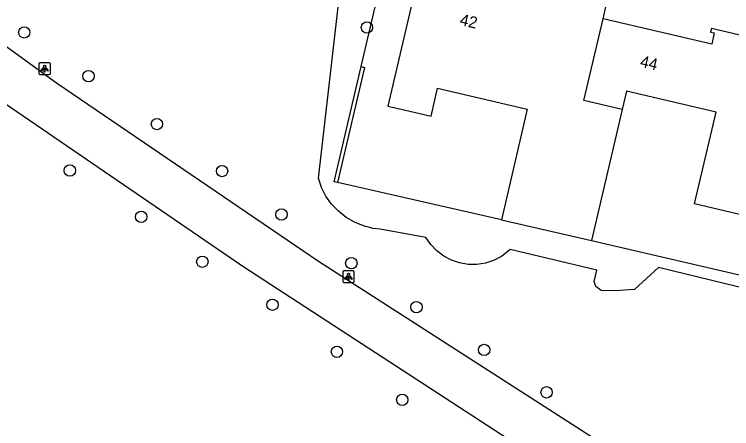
# Model space of a CAD drawing. Extents: x 162186 to 163152, y 385513 to 386513.
# Drawn here: x 162525.5 to 162587.2, y 385631 to 385666.6 of the extents above; entities that cross this region are included whole.
import ezdxf

# ---------------------------------------------------------------- set-up
doc = ezdxf.new("R2010")
doc.units = 0
for name, color, linetype in [('IMGEO_Boom', 7, 'Continuous'), ('IMGEO_Groenvoorziening', 7, 'Continuous'), ('IMGEO_Lichtpunt', 7, 'Continuous'), ('IMGEO_Muur', 7, 'Continuous'), ('IMGEO_Pand', 7, 'Continuous'), ('IMGEO_Pand_nummerreeks', 7, 'Continuous'), ('IMGEO_Voetpad_open', 7, 'Continuous')]:
    doc.layers.add(name, color=color, linetype=linetype)

msp = doc.modelspace()

# ---------------------------------------------------------------- linework, layer by layer
at = {"layer": 'IMGEO_Boom'}
for centre in [(162555.837, 385665.43), (162526.381, 385665.007), (162531.9, 385661.249), (162537.788, 385657.136), (162530.293, 385653.142), (162543.384, 385653.098), (162536.434, 385649.169), (162548.496, 385649.364), (162541.687, 385645.309), (162554.499, 385645.188), (162547.714, 385641.615), (162560.094, 385641.404), (162553.259, 385637.577), (162565.917, 385637.735), (162571.284, 385634.091), (162558.88, 385633.451)]:
    msp.add_circle(centre, 0.489, dxfattribs=at)
at = {"layer": 'IMGEO_Groenvoorziening'}
for points in [[(162591.033, 385642.365), (162580.904, 385644.813), (162578.838, 385642.928), (162577.137, 385642.809), (162575.982, 385642.845), (162575.524, 385643.186), (162575.383, 385643.605), (162575.605, 385644.575), (162568.163, 385646.362), (162567.994, 385646.207), (162567.394, 385645.764), (162566.732, 385645.422), (162566.023, 385645.191), (162565.286, 385645.076), (162564.54, 385645.081), (162563.805, 385645.206), (162563.099, 385645.446), (162562.441, 385645.796), (162561.847, 385646.248), (162561.333, 385646.788), (162560.913, 385647.404), (162556.969, 385648.1), (162556.363, 385648.174), (162555.546, 385648.378), (162554.766, 385648.696), (162554.04, 385649.121), (162553.381, 385649.645), (162552.803, 385650.257), (162552.318, 385650.945), (162551.936, 385651.695), (162551.664, 385652.492), (162554.918, 385680.665)], [(162555.341, 385662.064), (162557.55, 385671.508), (162558.184, 385674.374)], [(162567.404, 385648.918), (162553.321, 385652.112)], [(162575.152, 385647.123), (162606.008, 385639.975), (162607.236, 385639.664)]]:
    msp.add_lwpolyline(points, dxfattribs=at)
at = {"layer": 'IMGEO_Lichtpunt'}
for p, q in [((162527.624, 385662.29), (162527.624, 385661.483)), ((162527.624, 385662.29), (162527.624, 385661.483)), ((162528.526, 385662.385), (162527.718, 385662.385)), ((162528.526, 385662.385), (162527.718, 385662.385)), ((162528.62, 385661.483), (162528.62, 385662.29)), ((162528.62, 385661.483), (162528.62, 385662.29)), ((162527.718, 385661.389), (162528.526, 385661.389)), ((162527.718, 385661.389), (162528.526, 385661.389)), ((162553.756, 385644.422), (162553.756, 385643.615)), ((162553.756, 385644.422), (162553.756, 385643.615)), ((162554.658, 385644.517), (162553.85, 385644.517)), ((162554.658, 385644.517), (162553.85, 385644.517)), ((162554.752, 385643.615), (162554.752, 385644.422)), ((162554.752, 385643.615), (162554.752, 385644.422)), ((162553.85, 385643.521), (162554.658, 385643.521)), ((162553.85, 385643.521), (162554.658, 385643.521))]:
    msp.add_line(p, q, dxfattribs=at)
for points in [[(162527.998, 385661.954), (162528.037, 385661.926), (162527.849, 385661.664), (162527.811, 385661.691), (162527.998, 385661.954)], [(162528.21, 385661.926), (162528.248, 385661.953), (162528.435, 385661.691), (162528.396, 385661.663), (162528.21, 385661.926)], [(162528.1, 385661.906), (162528.147, 385661.906), (162528.147, 385661.584), (162528.1, 385661.584), (162528.1, 385661.906)], [(162554.13, 385644.086), (162554.169, 385644.058), (162553.981, 385643.796), (162553.943, 385643.823), (162554.13, 385644.086)], [(162554.342, 385644.058), (162554.38, 385644.085), (162554.567, 385643.823), (162554.528, 385643.795), (162554.342, 385644.058)], [(162554.232, 385644.038), (162554.279, 385644.038), (162554.279, 385643.716), (162554.232, 385643.716), (162554.232, 385644.038)]]:
    msp.add_lwpolyline(points, dxfattribs=at)
for centre in [(162528.123, 385662.088), (162554.255, 385644.22)]:
    msp.add_circle(centre, 0.0994, dxfattribs=at)
for centre, start, end in [((162527.718, 385662.29), 90, 180), ((162527.718, 385662.29), 90, 180), ((162528.526, 385662.29), 0, 90), ((162528.526, 385662.29), 0, 90), ((162527.718, 385661.483), 180, 270), ((162527.718, 385661.483), 180, 270), ((162528.526, 385661.483), 270, 0), ((162528.526, 385661.483), 270, 360), ((162553.85, 385644.422), 90, 180), ((162553.85, 385644.422), 90, 180), ((162554.658, 385644.422), 0, 90), ((162554.658, 385644.422), 0, 90), ((162553.85, 385643.615), 180, 270), ((162553.85, 385643.615), 180, 270), ((162554.658, 385643.615), 270, 0), ((162554.658, 385643.615), 270, 360)]:
    msp.add_arc(centre, 0.0946, start, end, dxfattribs=at)
at = {"layer": 'IMGEO_Muur'}
for points in [[(162553.321, 385652.112), (162553.028, 385652.18), (162555.341, 385662.064)], [(162555.341, 385662.064), (162555.634, 385661.996), (162553.321, 385652.112)]]:
    msp.add_lwpolyline(points, dxfattribs=at)
at = {"layer": 'IMGEO_Pand'}
for points in [[(162576.142, 385666.171), (162576.44, 385667.446), (162569.932, 385668.969), (162569.851, 385668.626), (162570.233, 385668.537), (162570.004, 385667.559), (162560.619, 385669.755), (162560.847, 385670.73), (162560.47, 385670.819), (162557.628, 385658.67), (162559.148, 385658.314), (162561.35, 385657.798), (162561.919, 385660.229), (162569.628, 385658.426), (162567.404, 385648.918)], [(162577.788, 385658.393), (162574.495, 385659.164), (162576.142, 385666.171)], [(162591.646, 385662.588), (162591.937, 385663.833), (162585.45, 385665.351), (162585.375, 385665.031), (162585.704, 385664.954), (162585.478, 385663.987), (162576.142, 385666.171)], [(162593.256, 385654.774), (162591.777, 385648.451), (162584.008, 385650.269), (162585.855, 385658.163), (162578.156, 385659.964), (162577.788, 385658.393)], [(162577.788, 385658.393), (162575.152, 385647.123)], [(162567.404, 385648.918), (162575.152, 385647.123)]]:
    msp.add_lwpolyline(points, dxfattribs=at)
at = {"layer": 'IMGEO_Voetpad_open'}
for points in [[(162590.753, 385611.032), (162590.826, 385611.301), (162590.875, 385611.575), (162590.9, 385611.852), (162590.899, 385612.131), (162590.874, 385612.408), (162590.824, 385612.682), (162590.749, 385612.95), (162590.717, 385613.044), (162589.57, 385616.052), (162545.173, 385644.904), (162522.989, 385660.038), (162509.786, 385669.859), (162500, 385677.476), (162489.158, 385686.52), (162482.082, 385694.093), (162479.353, 385697.299)], [(162595.828, 385618.758), (162595.577, 385618.641), (162595.317, 385618.546), (162595.05, 385618.475), (162594.777, 385618.429), (162594.502, 385618.407), (162594.225, 385618.409), (162593.95, 385618.436), (162593.678, 385618.488), (162593.412, 385618.564), (162592.871, 385618.869), (162551.663, 385645.322), (162529.138, 385660.657), (162515.097, 385670.829), (162506.139, 385677.653), (162500, 385682.629), (162490.925, 385690.506), (162488.1, 385693.633), (162486.021, 385696.149)]]:
    msp.add_lwpolyline(points, dxfattribs=at)

# ---------------------------------------------------------------- texts
at = {"layer": 'IMGEO_Pand_nummerreeks'}
for s, rotation, p in [('42', 346.83028, (162563.756, 385665.652)), ('44', 346.83339, (162579.257, 385662.073))]:
    msp.add_text(s, height=1, rotation=rotation, dxfattribs=at).set_placement(p)

doc.saveas('drawing.dxf')
